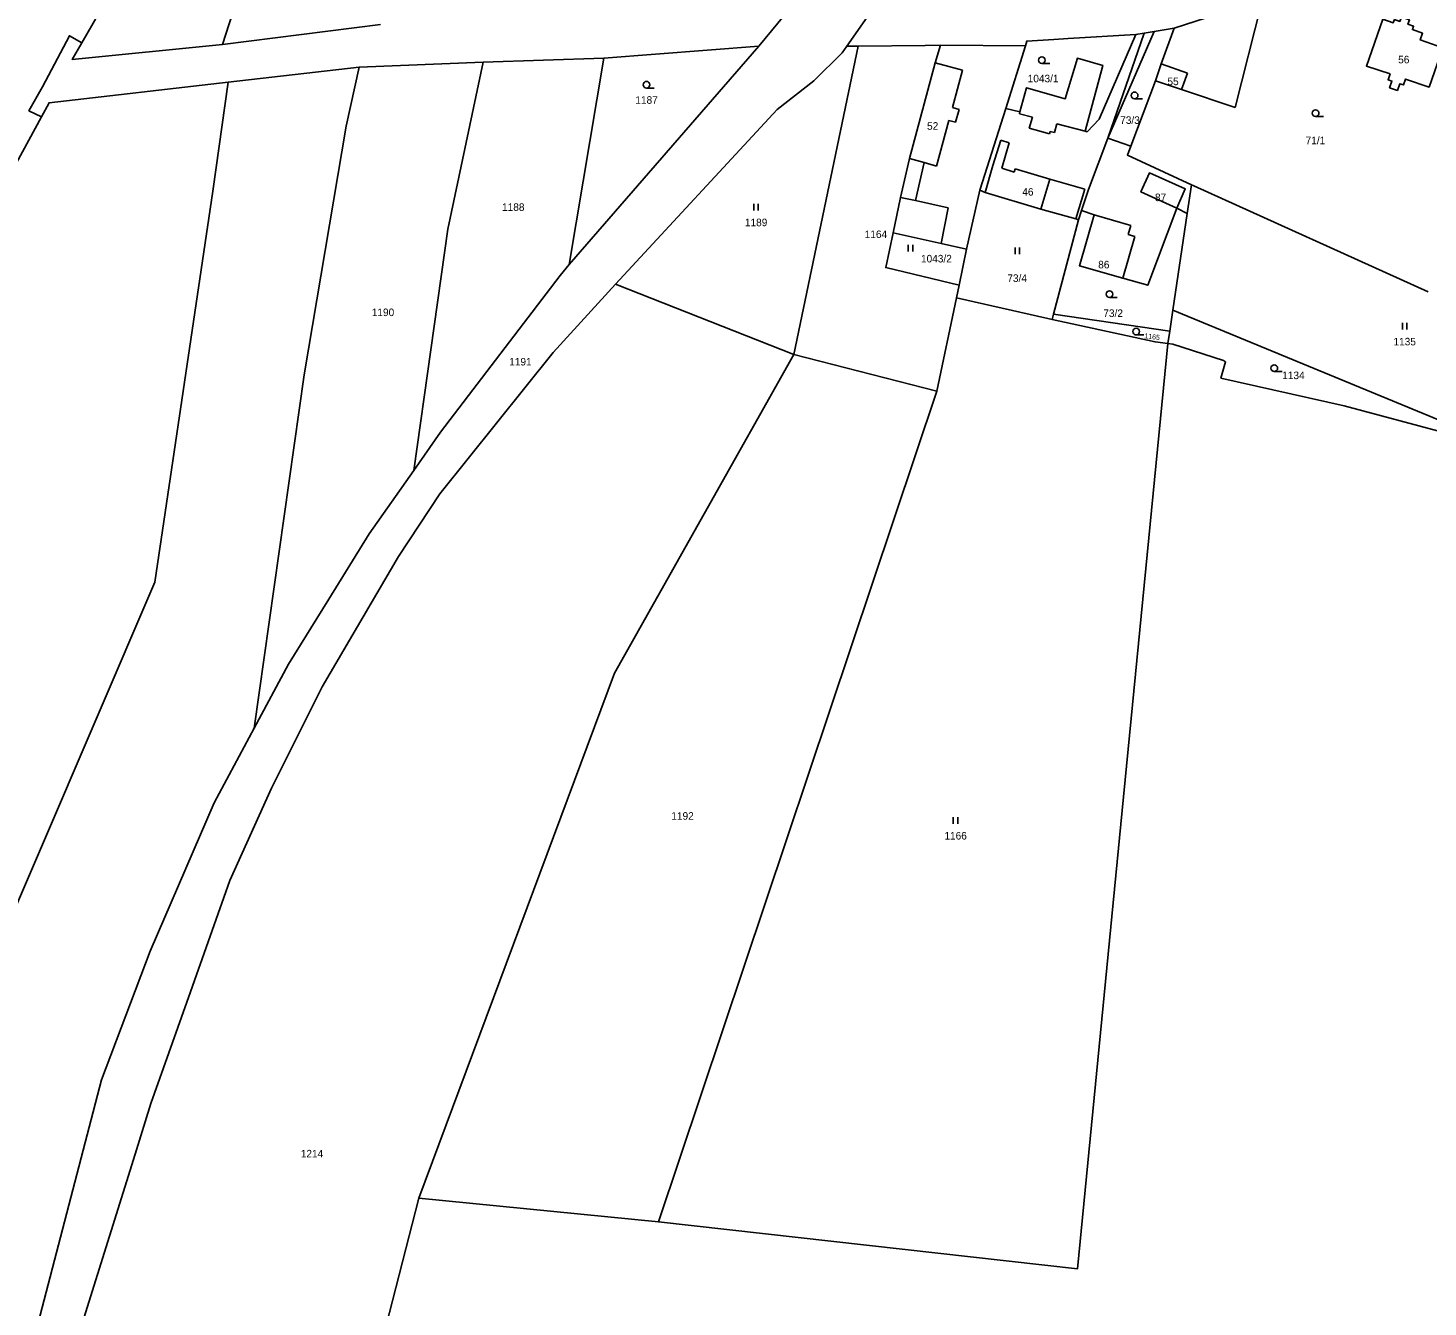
# Model space of a CAD drawing. Extents: x -746176 to -739709, y -1128407 to -1124482.
# Drawn here: x -742787.6 to -742472.1, y -1126240.2 to -1125952.1 of the extents above; entities that cross this region are included whole.
import ezdxf

# ---------------------------------------------------------------- set-up
doc = ezdxf.new("R2010")
doc.units = 0
for name, color, linetype in [('Hranice parcel', 7, 'Continuous'), ('Parcelní čísla', 7, 'Continuous'), ('Vnitřní kresba', 7, 'Continuous'), ('Značky kultur', 7, 'Continuous')]:
    doc.layers.add(name, color=color, linetype=linetype)

msp = doc.modelspace()

# ---------------------------------------------------------------- linework, layer by layer
at = {"layer": 'Hranice parcel'}
for p, q in [((-742743.77, -1125955.79), (-742708.2, -1125951.28)), ((-742544.26, -1125976.88), (-742536.12, -1125953.2)), ((-742536.12, -1125953.2), (-742537.98, -1125953.5)), ((-742665.65, -1126005.37), (-742622.9, -1125956.15)), ((-742622.9, -1125956.15), (-742657.81, -1125958.9)), ((-742600.52, -1125956.13), (-742615.01, -1126025.64)), ((-742603.12, -1125956.16), (-742600.52, -1125956.13)), ((-742562.86, -1125956.05), (-742581.95, -1125955.95)), ((-742567.25, -1125970.2), (-742562.86, -1125956.05)), ((-742712.96, -1125960.87), (-742742.47, -1125964.26)), ((-742685, -1125959.73), (-742712.96, -1125960.87)), ((-742657.81, -1125958.9), (-742685, -1125959.73)), ((-742657.81, -1125958.9), (-742665.65, -1126005.37)), ((-742539.1, -1125978.71), (-742533.51, -1125963.98)), ((-742567.25, -1125970.2), (-742573.08, -1125988.58)), ((-742544.26, -1125976.88), (-742539.1, -1125978.71)), ((-742576.14, -1126001.93), (-742573.08, -1125988.58)), ((-742526.38, -1125993.88), (-742525.42, -1125987.39)), ((-742550.91, -1125995.29), (-742550.22, -1125993.2)), ((-742550.91, -1125995.29), (-742556.49, -1126016.56)), ((-742529.61, -1126015.62), (-742526.38, -1125993.88)), ((-742576.14, -1126001.93), (-742577.78, -1126009.98)), ((-742655.18, -1126009.8), (-742615.01, -1126025.64)), ((-742577.78, -1126009.98), (-742578.37, -1126012.89)), ((-742582.8, -1126033.87), (-742578.37, -1126012.89)), ((-742556.81, -1126017.77), (-742556.49, -1126016.56)), ((-742556.49, -1126016.56), (-742530.31, -1126020.34)), ((-742530.31, -1126020.34), (-742529.61, -1126015.62)), ((-742452.02, -1126047.65), (-742529.61, -1126015.62)), ((-742530.31, -1126020.34), (-742530.79, -1126023.12)), ((-742615.01, -1126025.64), (-742582.8, -1126033.87)), ((-742582.8, -1126033.87), (-742645.51, -1126221.02)), ((-742699.51, -1126215.67), (-742742.72, -1126384.02)), ((-742645.51, -1126221.02), (-742699.51, -1126215.67))]:
    msp.add_line(p, q, dxfattribs=at)
for points in [[(-742718.28, -1125853.63), (-742740.52, -1125893.64), (-742764.97, -1125937.08), (-742775.44, -1125955.39)], [(-742706.55, -1125858.76), (-742721.46, -1125891.59), (-742729.1, -1125910.37), (-742743.77, -1125955.79)], [(-742622.9, -1125956.15), (-742614.33, -1125945.77), (-742586.39, -1125918.45), (-742565.5, -1125896.03), (-742552.77, -1125881.87), (-742549.27, -1125878.06)], [(-742588.9, -1125948.74), (-742597.47, -1125948.09), (-742603.12, -1125956.16)], [(-742533.51, -1125963.98), (-742527.67, -1125965.96), (-742515.61, -1125969.96), (-742509.68, -1125946.54)], [(-742509.68, -1125946.54), (-742515.14, -1125947.5), (-742529.35, -1125952.1)], [(-742529.35, -1125952.1), (-742533.86, -1125952.83), (-742536.12, -1125953.2)], [(-742533.51, -1125963.98), (-742532.24, -1125960.14), (-742529.35, -1125952.1)], [(-742480.68, -1125962.42), (-742481.12, -1125963.73), (-742480.27, -1125964.02), (-742480.78, -1125965.52), (-742479, -1125966.12), (-742478.49, -1125964.62), (-742477.64, -1125964.9), (-742477.2, -1125963.59), (-742471.89, -1125965.38), (-742468.82, -1125956.52), (-742473.86, -1125954.74), (-742473.34, -1125953.24), (-742475.63, -1125952.43), (-742475.36, -1125951.69), (-742476.67, -1125951.22), (-742476.32, -1125950.24), (-742478.09, -1125949.62), (-742478.44, -1125950.6), (-742479.71, -1125950.15), (-742479.97, -1125950.9), (-742482.31, -1125950.08), (-742485.99, -1125960.63), (-742480.68, -1125962.42)], [(-742775.44, -1125955.39), (-742778.28, -1125953.83), (-742784.34, -1125965.33), (-742787.4, -1125970.7), (-742784.59, -1125972.1)], [(-742537.98, -1125953.5), (-742546.21, -1125972.61), (-742548.93, -1125975.45), (-742549.4, -1125975.3), (-742545.39, -1125960.48), (-742551.14, -1125958.9), (-742553.87, -1125967.99), (-742562.62, -1125965.54), (-742564.09, -1125970.98), (-742567.25, -1125970.2)], [(-742537.98, -1125953.5), (-742553.22, -1125954.47), (-742556.43, -1125954.63), (-742562.53, -1125955), (-742562.86, -1125956.05)], [(-742775.44, -1125955.39), (-742777.62, -1125959.2), (-742743.77, -1125955.79)], [(-742603.12, -1125956.16), (-742604.17, -1125957.67), (-742610.51, -1125963.94), (-742618.75, -1125970.4), (-742655.18, -1126009.8)], [(-742600.52, -1125956.13), (-742585.45, -1125955.99), (-742581.95, -1125955.95)], [(-742581.95, -1125955.95), (-742583.15, -1125959.95), (-742588.97, -1125981.49), (-742591.02, -1125990.22), (-742592.66, -1125998.23)], [(-742712.96, -1125960.87), (-742715.93, -1125974.15), (-742725.36, -1126030.21), (-742736.67, -1126109.84)], [(-742685, -1125959.73), (-742693.03, -1125997.36), (-742700.69, -1126051.75)], [(-742742.47, -1125964.26), (-742745.94, -1125988.79), (-742759.05, -1126076.89), (-742837.32, -1126259.46)], [(-742784.59, -1125972.1), (-742782.85, -1125968.91), (-742742.47, -1125964.26)], [(-742784.59, -1125972.1), (-742795.62, -1125992.31), (-742808.96, -1126016.78), (-742827.59, -1126050.19), (-742855.36, -1126099.81), (-742870.35, -1126126.4), (-742896.52, -1126158.41), (-742949.69, -1126201.25), (-742989.75, -1126232.5), (-743025.91, -1126260.95), (-743057.91, -1126286.02), (-743099.7, -1126317.73)], [(-742550.22, -1125993.2), (-742548.63, -1125988.42), (-742544.26, -1125976.88)], [(-742525.42, -1125987.39), (-742539.86, -1125980.7), (-742539.1, -1125978.71)], [(-742528.71, -1125992.67), (-742536.8, -1125989.01), (-742534.92, -1125984.73), (-742526.82, -1125988.31), (-742528.71, -1125992.67)], [(-742573.08, -1125988.58), (-742571.93, -1125989.09), (-742559.35, -1125992.89), (-742551.46, -1125995.07), (-742550.91, -1125995.29)], [(-742525.42, -1125987.39), (-742524.92, -1125987.63), (-742472.11, -1126011.47)], [(-742550.22, -1125993.2), (-742547.37, -1125994.19), (-742550.69, -1126005.62), (-742540.91, -1126008.42), (-742535.29, -1126010.02), (-742528.71, -1125992.67), (-742526.38, -1125993.88)], [(-742592.66, -1125998.23), (-742594.32, -1126006.04), (-742577.78, -1126009.98)], [(-742592.66, -1125998.23), (-742581.83, -1126000.58), (-742576.14, -1126001.93)], [(-742700.69, -1126051.75), (-742694.64, -1126043.11), (-742667.67, -1126007.81), (-742665.65, -1126005.37)], [(-742655.18, -1126009.8), (-742669.27, -1126025.18), (-742694.82, -1126057.02), (-742704.11, -1126071.12), (-742721.29, -1126100.47), (-742732.76, -1126123.33), (-742742.1, -1126144.14), (-742751, -1126169.24), (-742759.9, -1126194.33), (-742763.48, -1126205.79), (-742783.53, -1126269.84), (-742800.78, -1126331.04), (-742814.62, -1126379.12)], [(-742578.37, -1126012.89), (-742557.79, -1126017.55), (-742556.81, -1126017.77)], [(-742530.79, -1126023.12), (-742533.62, -1126022.77), (-742556.81, -1126017.77)], [(-742530.79, -1126023.12), (-742541.03, -1126128.32), (-742551.09, -1126231.6), (-742645.51, -1126221.02)], [(-742530.79, -1126023.12), (-742529.6, -1126023.26), (-742518.21, -1126026.98), (-742517.74, -1126027.24), (-742518.78, -1126030.97), (-742491.05, -1126037.15), (-742452.02, -1126047.65)], [(-742615.01, -1126025.64), (-742655.41, -1126097.45), (-742699.51, -1126215.67)], [(-742736.67, -1126109.84), (-742728.93, -1126095.41), (-742719.82, -1126080.73), (-742710.71, -1126066.05), (-742700.69, -1126051.75)], [(-742793.63, -1126275.74), (-742771.03, -1126189.05), (-742760.08, -1126160.03), (-742745.65, -1126126.59), (-742736.67, -1126109.84)]]:
    msp.add_lwpolyline(points, dxfattribs=at)
at = {"layer": 'Vnitřní kresba'}
for p, q in [((-742544.26, -1125976.88), (-742533.86, -1125952.83)), ((-742583.15, -1125959.95), (-742577.01, -1125961.58)), ((-742579.3, -1125969.99), (-742577.01, -1125961.58)), ((-742532.24, -1125960.14), (-742526.35, -1125962.21)), ((-742527.67, -1125965.96), (-742526.35, -1125962.21)), ((-742579.3, -1125969.99), (-742577.8, -1125970.4)), ((-742578.59, -1125973.3), (-742577.8, -1125970.4)), ((-742564.2, -1125971.41), (-742564.09, -1125970.98)), ((-742582.89, -1125983.16), (-742580.09, -1125972.89)), ((-742580.09, -1125972.89), (-742578.59, -1125973.3)), ((-742564.2, -1125971.41), (-742561.24, -1125972.19)), ((-742562.02, -1125974.66), (-742561.24, -1125972.19)), ((-742556.28, -1125975.62), (-742555.76, -1125973.63)), ((-742555.76, -1125973.63), (-742549.4, -1125975.3)), ((-742570.16, -1125983.03), (-742568.42, -1125977.34)), ((-742568.42, -1125977.34), (-742566.48, -1125977.96)), ((-742562.02, -1125974.66), (-742557.45, -1125975.89)), ((-742557.45, -1125975.89), (-742557.3, -1125975.35)), ((-742557.3, -1125975.35), (-742556.28, -1125975.62)), ((-742568.14, -1125983.67), (-742566.48, -1125977.96)), ((-742588.97, -1125981.49), (-742585.64, -1125982.4)), ((-742587.58, -1125990.96), (-742585.64, -1125982.4)), ((-742585.64, -1125982.4), (-742582.89, -1125983.16)), ((-742571.93, -1125989.09), (-742570.16, -1125983.03)), ((-742568.14, -1125983.67), (-742565.4, -1125984.52)), ((-742565.4, -1125984.52), (-742565.18, -1125983.78)), ((-742565.18, -1125983.78), (-742557.33, -1125986.12)), ((-742559.35, -1125992.89), (-742557.33, -1125986.12)), ((-742557.33, -1125986.12), (-742549.43, -1125988.35)), ((-742551.46, -1125995.07), (-742549.43, -1125988.35)), ((-742591.02, -1125990.22), (-742587.58, -1125990.96)), ((-742587.58, -1125990.96), (-742580.28, -1125992.55)), ((-742581.83, -1126000.58), (-742580.28, -1125992.55)), ((-742547.37, -1125994.19), (-742539.06, -1125996.58)), ((-742540.91, -1126008.42), (-742538.2, -1125999.01)), ((-742539.69, -1125998.58), (-742539.06, -1125996.58)), ((-742539.69, -1125998.58), (-742538.2, -1125999.01))]:
    msp.add_line(p, q, dxfattribs=at)
at = {"layer": 'Značky kultur'}
for p, q in [((-742559.13, -1125960.05), (-742557.38, -1125960.05)), ((-742648.22, -1125965.59), (-742646.47, -1125965.59)), ((-742538.24, -1125968), (-742536.49, -1125968)), ((-742497.45, -1125971.99), (-742495.7, -1125971.99)), ((-742624.06, -1125993.17), (-742624.06, -1125991.67)), ((-742623.06, -1125993.17), (-742623.06, -1125991.67)), ((-742589.23, -1126002.43), (-742589.23, -1126000.93)), ((-742588.23, -1126002.43), (-742588.23, -1126000.93)), ((-742565.19, -1126003.03), (-742565.19, -1126001.53)), ((-742564.19, -1126003.03), (-742564.19, -1126001.53)), ((-742543.91, -1126012.77), (-742542.16, -1126012.77)), ((-742537.89, -1126021.22), (-742536.14, -1126021.22)), ((-742477.91, -1126020.02), (-742477.91, -1126018.52)), ((-742476.91, -1126020.02), (-742476.91, -1126018.52)), ((-742506.76, -1126029.47), (-742505.01, -1126029.47)), ((-742579.1, -1126131.34), (-742579.1, -1126129.84)), ((-742578.1, -1126131.34), (-742578.1, -1126129.84))]:
    msp.add_line(p, q, dxfattribs=at)
for centre in [(-742559.13, -1125959.3), (-742648.22, -1125964.84), (-742538.24, -1125967.25), (-742497.45, -1125971.24), (-742543.91, -1126012.02), (-742537.89, -1126020.47), (-742506.76, -1126028.72)]:
    msp.add_circle(centre, 0.75, dxfattribs=at)

# ---------------------------------------------------------------- texts
at = {"layer": 'Parcelní čísla'}
for s, p in [('56', (-742478.85, -1125960.03)), ('1043/1', (-742562.33, -1125964.3)), ('55', (-742530.84, -1125964.95)), ('1187', (-742650.74, -1125969.14)), ('52', (-742585.01, -1125974.99)), ('73/3', (-742541.49, -1125973.67)), ('71/1', (-742499.7, -1125978.24)), ('46', (-742563.55, -1125989.82)), ('87', (-742533.65, -1125991.07)), ('1188', (-742680.78, -1125993.27)), ('1189', (-742626.06, -1125996.72)), ('1164', (-742599.06, -1125999.39)), ('1043/2', (-742586.38, -1126004.88)), ('86', (-742546.45, -1126006.22)), ('73/4', (-742566.92, -1126009.28)), ('1190', (-742710.14, -1126016.97)), ('73/2', (-742545.29, -1126017.17)), ('1135', (-742479.91, -1126023.57)), ('1191', (-742679.17, -1126028.1)), ('1134', (-742504.98, -1126031.17)), ('1192', (-742642.64, -1126130.43)), ('1166', (-742581.1, -1126134.89)), ('1214', (-742726.14, -1126206.51))]:
    msp.add_text(s, height=1.7, dxfattribs=at).set_placement(p)
msp.add_text('1165', height=1.14, rotation=353, dxfattribs=at).set_placement((-742536.09, -1126021.95))

doc.saveas('drawing.dxf')
